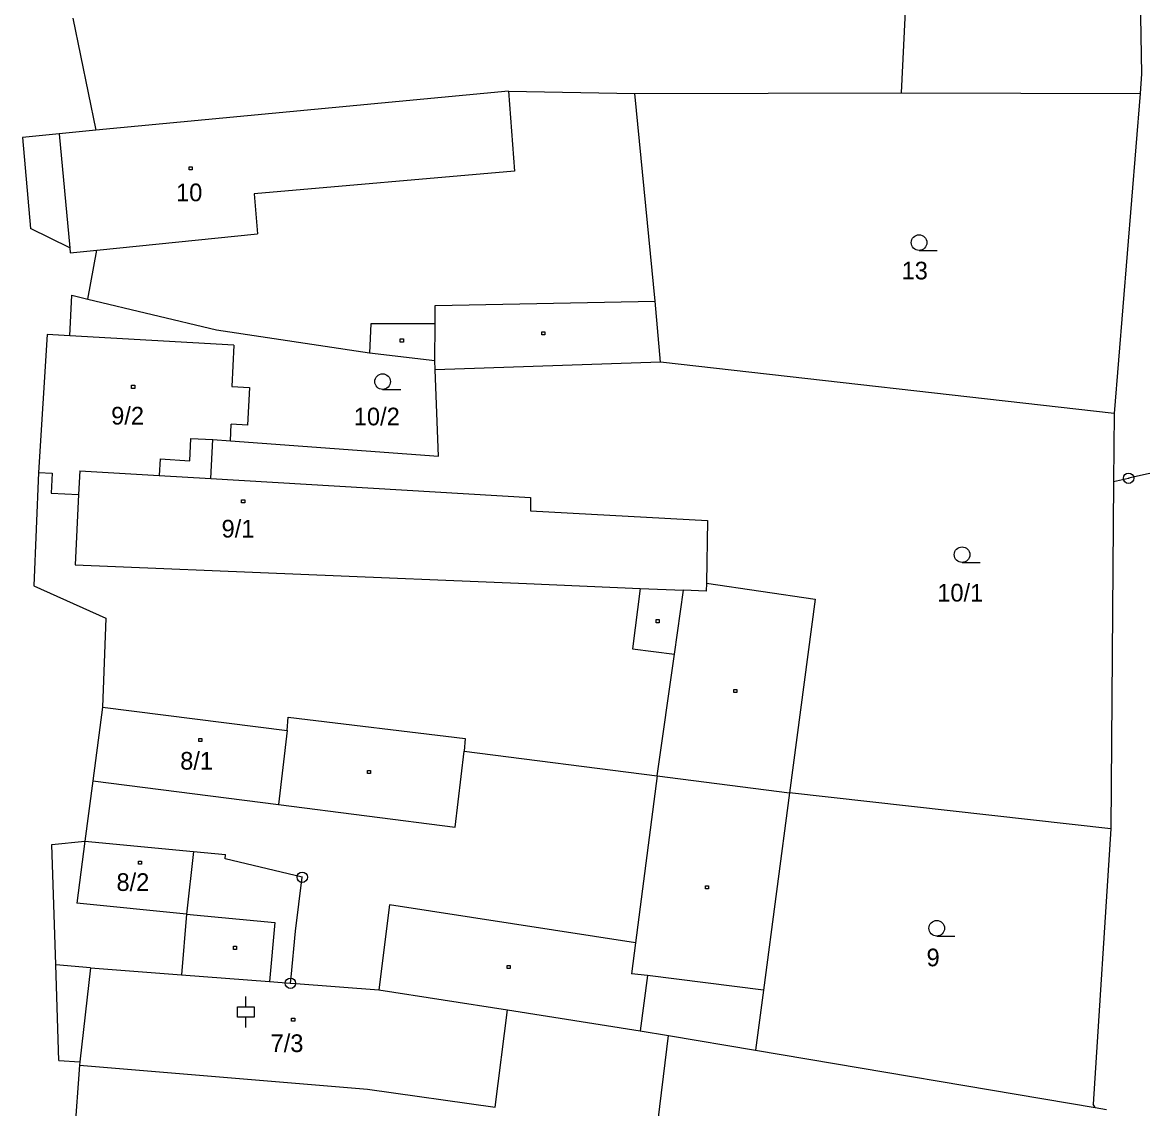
# Model space of a CAD drawing. Extents: x -794142 to -791199, y -1109267 to -1105626.
# Drawn here: x -793452.8 to -793345, y -1107850.3 to -1107745.8 of the extents above; entities that cross this region are included whole.
import ezdxf

# ---------------------------------------------------------------- set-up
doc = ezdxf.new("R2010")
doc.units = 0
for name, color, linetype in [('Vrstva 1', 7, 'Continuous'), ('Vrstva 14', 7, 'Continuous'), ('Vrstva 15', 7, 'Continuous'), ('Vrstva 2', 7, 'Continuous'), ('Vrstva 23', 7, 'Continuous'), ('Vrstva 25', 7, 'Continuous'), ('Vrstva 28', 7, 'Continuous')]:
    doc.layers.add(name, color=color, linetype=linetype)

msp = doc.modelspace()

# ---------------------------------------------------------------- linework, layer by layer
at = {"layer": 'Vrstva 1'}
for p, q in [((-793345.71, -1107712.69), (-793345.12, -1107750.73)), ((-793368.19, -1107752.55), (-793367.55, -1107739.54)), ((-793447.91, -1107745.39), (-793445.71, -1107756.16)), ((-793345.12, -1107750.73), (-793345.24, -1107752.64)), ((-793405.99, -1107752.41), (-793445.71, -1107756.16)), ((-793405.99, -1107752.41), (-793393.86, -1107752.64)), ((-793393.86, -1107752.64), (-793368.19, -1107752.55)), ((-793391.88, -1107772.59), (-793393.86, -1107752.64)), ((-793368.19, -1107752.55), (-793345.24, -1107752.64)), ((-793345.24, -1107752.64), (-793347.74, -1107783.42)), ((-793449.22, -1107756.49), (-793452.76, -1107756.86)), ((-793452.76, -1107756.86), (-793451.97, -1107765.61)), ((-793445.71, -1107756.16), (-793449.22, -1107756.49)), ((-793448.21, -1107767.47), (-793451.97, -1107765.61)), ((-793448.21, -1107767.47), (-793448.17, -1107767.95)), ((-793448.17, -1107767.95), (-793445.61, -1107767.69)), ((-793446.48, -1107772.4), (-793445.61, -1107767.69)), ((-793448.21, -1107775.93), (-793448.01, -1107772.03)), ((-793448.01, -1107772.03), (-793446.48, -1107772.4)), ((-793446.48, -1107772.4), (-793434.09, -1107775.36)), ((-793391.37, -1107778.47), (-793391.88, -1107772.59)), ((-793450.39, -1107775.8), (-793451.2, -1107789.08)), ((-793448.21, -1107775.93), (-793450.39, -1107775.8)), ((-793432.42, -1107776.85), (-793448.21, -1107775.93)), ((-793434.09, -1107775.36), (-793419.37, -1107777.57)), ((-793432.42, -1107776.85), (-793432.61, -1107780.82)), ((-793419.37, -1107777.57), (-793413.09, -1107778.31)), ((-793413.04, -1107779.21), (-793413.09, -1107778.31)), ((-793391.37, -1107778.47), (-793413.04, -1107779.21)), ((-793347.74, -1107783.42), (-793391.37, -1107778.47)), ((-793412.75, -1107787.52), (-793413.04, -1107779.21)), ((-793432.61, -1107780.82), (-793430.93, -1107780.9)), ((-793430.93, -1107780.9), (-793431.1, -1107784.52)), ((-793347.74, -1107783.42), (-793347.79, -1107789.96)), ((-793432.74, -1107786.03), (-793432.68, -1107784.44)), ((-793431.1, -1107784.52), (-793432.68, -1107784.44)), ((-793436.67, -1107787.95), (-793436.55, -1107785.8)), ((-793436.55, -1107785.8), (-793434.44, -1107785.92)), ((-793434.62, -1107789.67), (-793434.44, -1107785.92)), ((-793434.44, -1107785.92), (-793432.74, -1107786.03)), ((-793432.74, -1107786.03), (-793412.75, -1107787.52)), ((-793439.52, -1107787.78), (-793439.61, -1107789.38)), ((-793439.52, -1107787.78), (-793436.67, -1107787.95)), ((-793451.2, -1107789.08), (-793451.67, -1107799.99)), ((-793451.2, -1107789.08), (-793449.89, -1107789.15)), ((-793449.89, -1107789.15), (-793449.98, -1107791.07)), ((-793447.24, -1107788.94), (-793447.35, -1107791.2)), ((-793447.24, -1107788.94), (-793439.61, -1107789.38)), ((-793340.56, -1107788.36), (-793346.35, -1107789.64)), ((-793434.62, -1107789.67), (-793403.9, -1107791.49)), ((-793347.79, -1107789.96), (-793348.05, -1107823.38)), ((-793347.79, -1107789.96), (-793346.35, -1107789.64)), ((-793449.98, -1107791.07), (-793447.35, -1107791.2)), ((-793403.9, -1107791.49), (-793403.9, -1107792.77)), ((-793403.9, -1107792.77), (-793386.87, -1107793.71)), ((-793386.87, -1107793.71), (-793386.97, -1107799.73)), ((-793451.67, -1107799.99), (-793444.72, -1107803.11)), ((-793386.97, -1107799.73), (-793376.51, -1107801.28)), ((-793376.51, -1107801.28), (-793378.97, -1107819.91)), ((-793444.72, -1107803.11), (-793445.07, -1107811.67)), ((-793445.07, -1107811.67), (-793446, -1107818.76)), ((-793445.07, -1107811.67), (-793427.3, -1107813.92)), ((-793427.3, -1107813.92), (-793427.21, -1107812.62)), ((-793427.21, -1107812.62), (-793410.16, -1107814.69)), ((-793410.16, -1107814.69), (-793410.28, -1107815.9)), ((-793410.28, -1107815.9), (-793391.7, -1107818.28)), ((-793391.7, -1107818.28), (-793378.97, -1107819.91)), ((-793446, -1107818.76), (-793446.74, -1107824.55)), ((-793378.97, -1107819.91), (-793381.47, -1107838.9)), ((-793348.05, -1107823.38), (-793378.97, -1107819.91)), ((-793348.05, -1107823.38), (-793349.77, -1107849.86)), ((-793449.94, -1107824.88), (-793446.74, -1107824.55)), ((-793446.74, -1107824.55), (-793436.29, -1107825.55)), ((-793449.56, -1107836.46), (-793449.94, -1107824.88)), ((-793436.29, -1107825.55), (-793433.22, -1107825.85)), ((-793433.25, -1107826.25), (-793433.22, -1107825.85)), ((-793425.84, -1107828.02), (-793433.25, -1107826.25)), ((-793426.49, -1107833.22), (-793425.84, -1107828.02)), ((-793426.92, -1107837.62), (-793426.49, -1107833.22)), ((-793449.26, -1107845.66), (-793449.56, -1107836.46)), ((-793446.22, -1107836.74), (-793449.56, -1107836.46)), ((-793446.22, -1107836.74), (-793437.46, -1107837.41)), ((-793437.46, -1107837.41), (-793429, -1107838.06)), ((-793426.98, -1107838.22), (-793426.92, -1107837.62)), ((-793429, -1107838.06), (-793426.98, -1107838.22)), ((-793426.98, -1107838.22), (-793426.45, -1107838.26)), ((-793426.45, -1107838.26), (-793418.47, -1107838.87)), ((-793418.47, -1107838.87), (-793406.09, -1107840.77)), ((-793381.47, -1107838.9), (-793382.23, -1107844.66)), ((-793406.09, -1107840.77), (-793393.33, -1107842.81)), ((-793393.33, -1107842.81), (-793390.61, -1107843.24)), ((-793392.43, -1107858.15), (-793390.61, -1107843.24)), ((-793390.61, -1107843.24), (-793382.23, -1107844.66)), ((-793382.23, -1107844.66), (-793349.56, -1107850.19)), ((-793449.26, -1107845.66), (-793447.22, -1107845.77)), ((-793447.26, -1107846.09), (-793447.78, -1107853.18)), ((-793447.22, -1107845.77), (-793447.26, -1107846.09)), ((-793349.56, -1107850.19), (-793349.77, -1107849.86)), ((-793349.56, -1107850.19), (-793348.49, -1107850.37))]:
    msp.add_line(p, q, dxfattribs=at)
at = {"layer": 'Vrstva 2'}
for p, q in [((-793405.99, -1107752.41), (-793405.41, -1107760.1)), ((-793449.22, -1107756.49), (-793448.21, -1107767.47)), ((-793405.41, -1107760.1), (-793430.48, -1107762.29)), ((-793430.48, -1107762.29), (-793430.14, -1107766.12)), ((-793445.61, -1107767.69), (-793430.14, -1107766.12)), ((-793413.07, -1107773.02), (-793391.88, -1107772.59)), ((-793413.06, -1107774.79), (-793413.07, -1107773.02)), ((-793419.25, -1107774.79), (-793419.37, -1107777.57)), ((-793413.06, -1107774.79), (-793419.25, -1107774.79)), ((-793413.09, -1107778.31), (-793413.06, -1107774.79)), ((-793439.61, -1107789.38), (-793434.62, -1107789.67)), ((-793447.35, -1107791.2), (-793447.7, -1107797.98)), ((-793447.7, -1107797.98), (-793404.27, -1107799.77)), ((-793404.27, -1107799.77), (-793393.32, -1107800.24)), ((-793386.97, -1107799.73), (-793386.98, -1107800.51)), ((-793393.32, -1107800.24), (-793394.08, -1107806.06)), ((-793393.32, -1107800.24), (-793389.17, -1107800.42)), ((-793390.04, -1107806.57), (-793389.17, -1107800.42)), ((-793386.98, -1107800.51), (-793389.17, -1107800.42)), ((-793394.08, -1107806.06), (-793390.04, -1107806.57)), ((-793391.7, -1107818.28), (-793390.04, -1107806.57)), ((-793427.3, -1107813.92), (-793428.13, -1107821.03)), ((-793411.13, -1107823.19), (-793410.28, -1107815.9)), ((-793391.7, -1107818.28), (-793393.79, -1107834.34)), ((-793446, -1107818.76), (-793428.13, -1107821.03)), ((-793428.13, -1107821.03), (-793411.13, -1107823.19)), ((-793446.74, -1107824.55), (-793447.51, -1107830.51)), ((-793436.29, -1107825.55), (-793436.97, -1107831.56)), ((-793436.97, -1107831.56), (-793447.51, -1107830.51)), ((-793417.45, -1107830.68), (-793418.47, -1107838.87)), ((-793393.79, -1107834.34), (-793417.45, -1107830.68)), ((-793436.97, -1107831.56), (-793437.46, -1107837.41)), ((-793436.97, -1107831.56), (-793428.48, -1107832.39)), ((-793428.48, -1107832.39), (-793429, -1107838.06)), ((-793393.79, -1107834.34), (-793394.17, -1107837.3)), ((-793446.22, -1107836.74), (-793447.22, -1107845.77)), ((-793392.64, -1107837.49), (-793394.17, -1107837.3)), ((-793392.64, -1107837.49), (-793393.33, -1107842.81)), ((-793381.47, -1107838.9), (-793392.64, -1107837.49)), ((-793407.28, -1107850.15), (-793406.09, -1107840.77)), ((-793447.26, -1107846.09), (-793419.58, -1107848.41)), ((-793419.58, -1107848.41), (-793407.28, -1107850.15))]:
    msp.add_line(p, q, dxfattribs=at)
at = {"layer": 'Vrstva 23'}
for p, q in [((-793366.51, -1107767.72), (-793364.76, -1107767.72)), ((-793418.11, -1107781.09), (-793416.36, -1107781.09)), ((-793362.37, -1107797.74), (-793360.62, -1107797.74)), ((-793364.81, -1107833.68), (-793363.06, -1107833.68)), ((-793431.27, -1107840.48), (-793431.27, -1107839.48)), ((-793432.07, -1107841.48), (-793432.07, -1107840.48)), ((-793432.07, -1107840.48), (-793430.47, -1107840.48)), ((-793430.47, -1107840.48), (-793430.47, -1107841.48)), ((-793430.47, -1107841.48), (-793432.07, -1107841.48)), ((-793431.27, -1107842.48), (-793431.27, -1107841.48))]:
    msp.add_line(p, q, dxfattribs=at)
for centre in [(-793366.51, -1107766.97), (-793418.11, -1107780.34), (-793362.37, -1107796.99), (-793364.81, -1107832.93)]:
    msp.add_circle(centre, 0.75, dxfattribs=at)
at = {"layer": 'Vrstva 25'}
for p, q in [((-793436.73, -1107759.67), (-793436.43, -1107759.67)), ((-793436.73, -1107759.97), (-793436.73, -1107759.67)), ((-793436.43, -1107759.97), (-793436.73, -1107759.97)), ((-793436.43, -1107759.67), (-793436.43, -1107759.97)), ((-793416.41, -1107776.24), (-793416.11, -1107776.24)), ((-793416.41, -1107776.54), (-793416.41, -1107776.24)), ((-793416.11, -1107776.24), (-793416.11, -1107776.54)), ((-793402.8, -1107775.54), (-793402.5, -1107775.54)), ((-793402.8, -1107775.84), (-793402.8, -1107775.54)), ((-793402.5, -1107775.84), (-793402.8, -1107775.84)), ((-793402.5, -1107775.54), (-793402.5, -1107775.84)), ((-793416.11, -1107776.54), (-793416.41, -1107776.54)), ((-793442.25, -1107780.69), (-793441.95, -1107780.69)), ((-793442.25, -1107780.99), (-793442.25, -1107780.69)), ((-793441.95, -1107780.99), (-793442.25, -1107780.99)), ((-793441.95, -1107780.69), (-793441.95, -1107780.99)), ((-793431.67, -1107791.71), (-793431.37, -1107791.71)), ((-793431.67, -1107792.01), (-793431.67, -1107791.71)), ((-793431.37, -1107792.01), (-793431.67, -1107792.01)), ((-793431.37, -1107791.71), (-793431.37, -1107792.01)), ((-793391.8, -1107803.24), (-793391.5, -1107803.24)), ((-793391.8, -1107803.54), (-793391.8, -1107803.24)), ((-793391.5, -1107803.24), (-793391.5, -1107803.54)), ((-793391.5, -1107803.54), (-793391.8, -1107803.54)), ((-793384.33, -1107809.96), (-793384.03, -1107809.96)), ((-793384.33, -1107810.26), (-793384.33, -1107809.96)), ((-793384.03, -1107810.26), (-793384.33, -1107810.26)), ((-793384.03, -1107809.96), (-793384.03, -1107810.26)), ((-793435.79, -1107814.66), (-793435.49, -1107814.66)), ((-793435.79, -1107814.96), (-793435.79, -1107814.66)), ((-793435.49, -1107814.96), (-793435.79, -1107814.96)), ((-793435.49, -1107814.66), (-793435.49, -1107814.96)), ((-793419.58, -1107817.74), (-793419.28, -1107817.74)), ((-793419.58, -1107818.04), (-793419.58, -1107817.74)), ((-793419.28, -1107818.04), (-793419.58, -1107818.04)), ((-793419.28, -1107817.74), (-793419.28, -1107818.04)), ((-793441.6, -1107826.47), (-793441.3, -1107826.47)), ((-793441.6, -1107826.77), (-793441.6, -1107826.47)), ((-793441.3, -1107826.77), (-793441.6, -1107826.77)), ((-793441.3, -1107826.47), (-793441.3, -1107826.77)), ((-793387.05, -1107828.84), (-793386.75, -1107828.84)), ((-793387.05, -1107829.14), (-793387.05, -1107828.84)), ((-793386.75, -1107829.14), (-793387.05, -1107829.14)), ((-793386.75, -1107828.84), (-793386.75, -1107829.14)), ((-793432.45, -1107834.66), (-793432.15, -1107834.66)), ((-793432.45, -1107834.96), (-793432.45, -1107834.66)), ((-793432.15, -1107834.96), (-793432.45, -1107834.96)), ((-793432.15, -1107834.66), (-793432.15, -1107834.96)), ((-793406.13, -1107836.5), (-793405.83, -1107836.5)), ((-793406.13, -1107836.8), (-793406.13, -1107836.5)), ((-793405.83, -1107836.5), (-793405.83, -1107836.8)), ((-793405.83, -1107836.8), (-793406.13, -1107836.8)), ((-793426.86, -1107841.58), (-793426.56, -1107841.58)), ((-793426.86, -1107841.88), (-793426.86, -1107841.58)), ((-793426.56, -1107841.88), (-793426.86, -1107841.88)), ((-793426.56, -1107841.58), (-793426.56, -1107841.88))]:
    msp.add_line(p, q, dxfattribs=at)
at = {"layer": 'Vrstva 28'}
for centre, radius in [((-793346.35, -1107789.64), 0.5), ((-793346.35, -1107789.64), 0.01), ((-793425.84, -1107828.02), 0.5), ((-793425.84, -1107828.02), 0.01), ((-793426.98, -1107838.22), 0.5), ((-793426.98, -1107838.22), 0.01)]:
    msp.add_circle(centre, radius, dxfattribs=at)

# ---------------------------------------------------------------- texts
at = {"layer": 'Vrstva 14'}
for s, p in [('13', (-793368.19, -1107770.51)), ('10/2', (-793420.882, -1107784.55)), ('10/1', (-793364.756, -1107801.5)), ('9', (-793365.787, -1107836.59))]:
    msp.add_text(s, height=1.7, dxfattribs=at).set_placement(p)
at = {"layer": 'Vrstva 15'}
for s, p in [('10', (-793437.979, -1107762.99)), ('9/2', (-793444.22, -1107784.47)), ('9/1', (-793433.603, -1107795.34)), ('8/1', (-793437.583, -1107817.67)), ('8/2', (-793443.71, -1107829.34)), ('7/3', (-793428.887, -1107844.84))]:
    msp.add_text(s, height=1.7, dxfattribs=at).set_placement(p)

doc.saveas('drawing.dxf')
